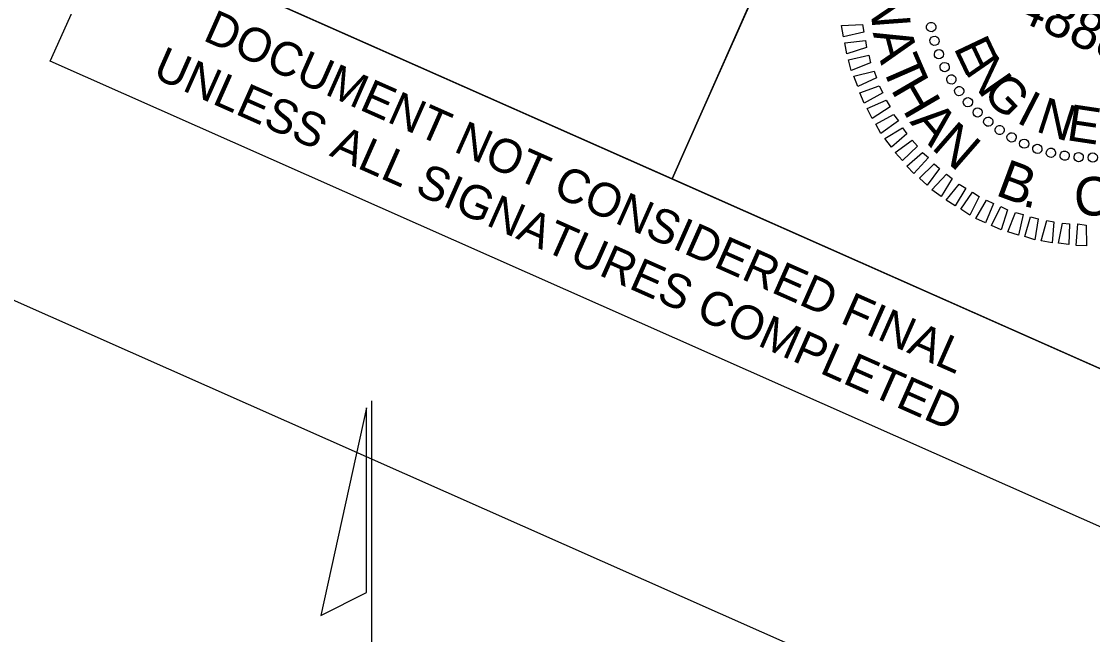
# Model space of a CAD drawing. Extents: x 1638962 to 2864602, y 841929 to 973236.
# Drawn here: x 1640662.4 to 1640836.4, y 842745.3 to 842844.8 of the extents above; entities that cross this region are included whole.
import ezdxf

# ---------------------------------------------------------------- set-up
doc = ezdxf.new("R2010")
doc.units = 0
for name, color, linetype in [('Default', 7, 'Continuous'), ('DEV STATIONARY SIGN DUAL MOUNT CELL', 7, 'Continuous'), ('Old_Level_2', 7, 'Continuous'), ('Prop Conc Drive Radius Type', 7, 'Continuous'), ('Prop EOT', 7, 'Continuous'), ('Scratch_Level_5', 7, 'Continuous')]:
    doc.layers.add(name, color=color, linetype=linetype)

msp = doc.modelspace()

# ---------------------------------------------------------------- linework, layer by layer
at = {"layer": 'DEV STATIONARY SIGN DUAL MOUNT CELL'}
msp.add_line((1640813.7, 842922.13), (1640768.13, 842819.32), dxfattribs=at)
for points in [[(1639123.48, 842564.09), (1639549.06, 843523.95), (1640737.47, 842997.04), (1640676.66, 842859.85), (1640859.52, 842778.75), (1640494.73, 841956.06)], [(1640722.24, 842962.69), (1640813.7, 842922.13), (1640768.1, 842819.28), (1640676.66, 842859.85)], [(1640813.7, 842922.13), (1640905.11, 842881.61), (1640859.52, 842778.75), (1640768.1, 842819.28)]]:
    msp.add_lwpolyline(points, close=True, dxfattribs=at)
at = {"layer": 'Old_Level_2'}
for p, q in [((1640810.15, 842843.9), (1640810.15, 842843.9)), ((1640810.64, 842841.71), (1640810.64, 842841.71)), ((1640811.41, 842839.51), (1640811.41, 842839.51)), ((1640812.29, 842837.43), (1640812.29, 842837.43)), ((1640813.43, 842835.42), (1640813.43, 842835.42)), ((1640814.65, 842833.48), (1640814.65, 842833.48)), ((1640816.13, 842831.72), (1640816.13, 842831.72)), ((1640817.69, 842830.04), (1640817.69, 842830.04)), ((1640819.42, 842828.51), (1640819.42, 842828.51)), ((1640821.26, 842827.22), (1640821.26, 842827.22)), ((1640823.19, 842826.01), (1640823.19, 842826.01)), ((1640825.25, 842824.97), (1640825.25, 842824.97)), ((1640827.39, 842824.12), (1640827.39, 842824.12)), ((1640829.58, 842823.54), (1640829.58, 842823.54)), ((1640831.86, 842823.03), (1640831.86, 842823.03)), ((1640834.13, 842822.75), (1640834.13, 842822.75))]:
    msp.add_line(p, q, dxfattribs=at)
for points in [[(1640799.25, 842843.11), (1640795.93, 842842.36), (1640795.62, 842844.19), (1640798.99, 842844.36)], [(1640799.67, 842840.61), (1640796.46, 842839.58), (1640796.13, 842841.37), (1640799.48, 842841.77)], [(1640800.32, 842838.12), (1640797.19, 842836.89), (1640796.73, 842838.62), (1640800.06, 842839.37)], [(1640801.28, 842835.67), (1640798.25, 842834.28), (1640797.58, 842835.93), (1640800.88, 842836.75)], [(1640802.3, 842833.25), (1640799.26, 842831.58), (1640798.6, 842833.23), (1640801.69, 842834.36)], [(1640803.5, 842830.99), (1640800.59, 842829.09), (1640799.79, 842830.68), (1640802.87, 842832.05)], [(1640804.86, 842828.71), (1640801.99, 842826.63), (1640801.17, 842828.17), (1640804.04, 842829.73)], [(1640806.19, 842826.61), (1640803.73, 842824.42), (1640802.63, 842825.85), (1640805.52, 842827.58)], [(1640807.94, 842824.57), (1640805.53, 842822.24), (1640804.32, 842823.54), (1640807.1, 842825.55)], [(1640809.72, 842822.74), (1640807.33, 842820.17), (1640806.22, 842821.32), (1640808.75, 842823.54)], [(1640811.52, 842820.96), (1640809.53, 842818.27), (1640808.24, 842819.39), (1640810.65, 842821.72)], [(1640813.56, 842819.35), (1640811.76, 842816.42), (1640810.28, 842817.5), (1640812.65, 842820.02)], [(1640815.8, 842817.78), (1640814.06, 842814.88), (1640812.57, 842815.8), (1640814.7, 842818.42)], [(1640817.95, 842816.42), (1640816.43, 842813.37), (1640814.96, 842814.33), (1640816.87, 842817.1)], [(1640820.29, 842815.26), (1640818.97, 842812.13), (1640817.4, 842812.85), (1640819.16, 842815.8)], [(1640822.58, 842814.23), (1640821.5, 842811), (1640819.93, 842811.72), (1640821.45, 842814.77)], [(1640825.09, 842813.46), (1640824.32, 842810.15), (1640822.6, 842810.65), (1640823.88, 842813.8)], [(1640827.53, 842812.77), (1640827, 842809.36), (1640825.35, 842809.89), (1640826.31, 842813.11)], [(1640830.06, 842812.32), (1640829.79, 842808.86), (1640828.01, 842809.21), (1640828.95, 842812.51)], [(1640832.64, 842811.97), (1640832.53, 842808.61), (1640830.85, 842808.81), (1640831.49, 842812.06)], [(1640835.33, 842811.74), (1640835.4, 842808.42), (1640833.71, 842808.45), (1640834, 842811.96)]]:
    msp.add_lwpolyline(points, close=True, dxfattribs=at)
for centre, major_axis in [((1640810.16, 842843.92), (-0.739, -0.145)), ((1640810.7, 842841.7), (-0.723, -0.209)), ((1640811.43, 842839.53), (-0.703, -0.271)), ((1640812.35, 842837.43), (-0.676, -0.331)), ((1640813.44, 842835.42), (-0.645, -0.389)), ((1640814.71, 842833.52), (-0.608, -0.443)), ((1640816.13, 842831.73), (-0.568, -0.495)), ((1640817.71, 842830.07), (-0.522, -0.542)), ((1640819.43, 842828.56), (-0.473, -0.586)), ((1640821.27, 842827.2), (-0.42, -0.625)), ((1640823.22, 842826.01), (-0.364, -0.659)), ((1640825.27, 842824.99), (-0.305, -0.688)), ((1640827.4, 842824.15), (-0.244, -0.712)), ((1640829.6, 842823.51), (-0.181, -0.731)), ((1640831.84, 842823.05), (-0.117, -0.744)), ((1640834.11, 842822.8), (-0.051, -0.751)), ((1640836.4, 842822.74), (0.014, -0.753))]:
    msp.add_ellipse(centre, major_axis=major_axis, ratio=0.999708, dxfattribs=at)
at = {"layer": 'Prop Conc Drive Radius Type'}
msp.add_line((1640719.36, 842653.24), (1640719.36, 842783.24), dxfattribs=at)
msp.add_lwpolyline([(1640718.46, 842782.1), (1640711.04, 842748.34), (1640718.46, 842752.1)], close=True, dxfattribs=at)
at = {"layer": 'Prop EOT'}
msp.add_lwpolyline([(1639169.19, 842543.82), (1640449.02, 841976.33), (1640788.91, 842742.87), (1640615.9, 842819.58), (1640701.62, 843012.92), (1639594.8, 843503.69)], close=True, dxfattribs=at)
at = {"layer": 'Scratch_Level_5'}
for p, q in [((1640667.13, 842838.37), (1640676.66, 842859.85)), ((1640667.13, 842838.37), (1640676.66, 842859.85)), ((1640676.66, 842859.85), (1640859.52, 842778.76)), ((1640676.66, 842859.85), (1640859.52, 842778.76)), ((1640850, 842757.28), (1640667.13, 842838.37)), ((1640850, 842757.28), (1640667.13, 842838.37))]:
    msp.add_line(p, q, dxfattribs=at)

# ---------------------------------------------------------------- texts
at = {"layer": 'Default'}
for s, rotation, p in [('N', 274.1644, (1640800.17, 842849.61)), ('A', 284.7762, (1640800.65, 842843.02)), ('T', 293.5225, (1640801.96, 842837.72)), ('H', 300.2504, (1640803.5, 842833.82)), ('A', 310.1283, (1640806.57, 842828.49)), ('N', 318.8746, (1640810.02, 842824.26)), ('B', 339.5782, (1640820.41, 842816.7)), ('C', 1.2758, (1640833.41, 842813.25)), ('.', 347.193, (1640824.81, 842814.93))]:
    msp.add_text(s, height=6.27, rotation=rotation, dxfattribs=at).set_placement(p)
at = {"layer": 'Old_Level_2'}
for s, height, rotation, p in [('048883', 6.275, 336.0871, (1640819.32, 842847.22)), ('E', 5.9, 295.364, (1640813.73, 842840.57)), ('N', 5.9, 304.7211, (1640815.52, 842836.75)), ('G', 5.9, 314.0774, (1640818.27, 842833.03)), ('I', 5.9, 332.7883, (1640823.8, 842828.53)), ('N', 5.9, 342.1435, (1640826.97, 842827.03)), ('E', 5.9, 351.4989, (1640831.98, 842825.59))]:
    msp.add_text(s, height=height, rotation=rotation, dxfattribs=at).set_placement(p)
at = {"layer": 'Scratch_Level_5'}
for s, p in [('DOCUMENT NOT CONSIDERED FINAL', (1640691.73, 842841.85)), ('DOCUMENT NOT CONSIDERED FINAL', (1640691.73, 842841.85)), ('UNLESS ALL SIGNATURES COMPLETED', (1640683.52, 842835.86)), ('UNLESS ALL SIGNATURES COMPLETED', (1640683.52, 842835.86))]:
    msp.add_text(s, height=5.5, rotation=336.0871, dxfattribs=at).set_placement(p)

doc.saveas('drawing.dxf')
